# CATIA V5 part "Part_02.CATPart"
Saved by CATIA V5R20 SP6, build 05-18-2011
Part number: Part_02
Bounding box of the stored display mesh (mm): x -8 to 8, y -18 to 5.5, z -5.5 to 13
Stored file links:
  E:\#01 CATIA Lecture Materials\#16 3D Print Test\3D Print Test\8th Test\Part_02.CATPart
  E:\#01 CATIA Lecture Materials\#16 3D Print Test\3D Print Test\2nd Test\3D Print Test_02.CATProduct
  E:\#01 CATIA Lecture Materials\#16 3D Print Test\3D Print Test\8th Test\Part_01.CATPart
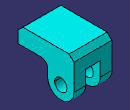
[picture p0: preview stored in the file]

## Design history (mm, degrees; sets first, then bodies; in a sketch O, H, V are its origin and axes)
Set1 "Reference Data"
  Point1 "Center Point": (0, 0, 0)
Body1 (main body)
Body2
  Sketch1 on yz-plane, origin (0, 0, 0), H (0, -1, 0), V (0, 0, 1)
    line L1 (-5.5, 13) -> (-5.5, 0)
    point P1 (-5.5, 0)
    arc A1 centre (0, 0) radius 5.5 from (-5.5, 0) to (5.5, 0) ccw
    line L2 (5.5, 0) -> (5.5, 6)
    line L3 (5.5, 6) -> (18, 6)
    line L4 (18, 6) -> (18, 13)
    line L5 (18, 13) -> (-5.5, 13)
    radius A1 = 5.5
    distance V L4 = 18
    distance L1 L4 = 23.5
    distance L3 L5 = 7
    distance H L3 = 6
    coincidence: P1 H
    vertical: L1 V, L4 V, L2 V
    tangency: A1 L1, L2 A1
    horizontal: L3 H, L5 H
  Pad1: profile Sketch1, direction (-1, 0, 0), length 8, mirrored extent
  Chamfer1: length 2, angle 45, on edge [face of Pad1 from Sketch1.L1 | face of Pad1 from Sketch1.L5]
  Chamfer2: length 2, angle 45, on edge [face of Pad1 from Sketch1.L5 | face of Pad1 from Sketch1.L4]
  Fillet1: radius 3, on edge [face of Pad1 from Sketch1.L3 | face of Pad1 from Sketch1.L2]
  Sketch2 on zx-plane, origin (0, 0, 0), H (1, 0, 0), V (0, 0, 1)
    line L1 (-3.1, 6) -> (3.1, 6)
    line L2 (3.1, 6) -> (3.1, -5.5)
    line L3 (3.1, -5.5) -> (-3.1, -5.5)
    line L4 (-3.1, -5.5) -> (-3.1, 6)
    reference projected line E1 (8, 13) -> (-8, 13) from edge [face of Pad1 from Sketch1.L5 | face of Chamfer2]
    reference projected line E2 (8, 13) -> (-8, 13) from edge [face of Pad1 from Sketch1.L5 | face of Chamfer2]
    distance L4 L2 = 6.2
    distance E1 L3 = 18.5
    distance E2 L1 = 7
    horizontal: L1 H, L3 H
    vertical: L2 V, L4 V
    symmetry: L4 L2 V
  Pocket1: profile Sketch2, direction (0, 1, 0), through (limit type 6), opposite side through (limit type 6)
  Sketch3 on yz-plane, origin (0, 0, 0), H (0, -1, 0), V (0, 0, 1)
    circle A1 centre (0, 0) radius 2.6
    radius A1 = 2.6
  Pocket2: profile Sketch3, direction (1, 0, 0), through (limit type 6), opposite side through (limit type 6)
